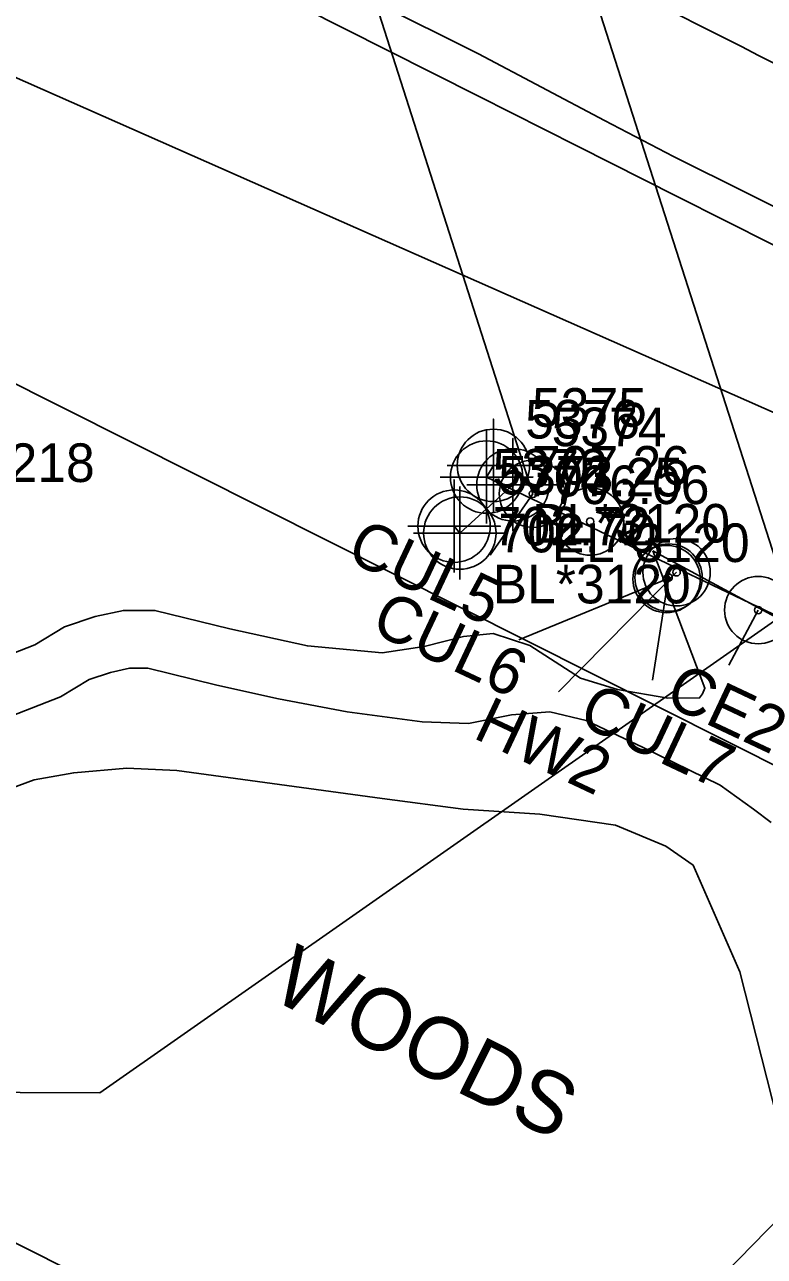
# Model space of a CAD drawing. Extents: x 1516784 to 1522736, y 634838 to 639369.
# Drawn here: x 1519934.1 to 1519982, y 638274.7 to 638354.5 of the extents above; entities that cross this region are included whole.
import ezdxf

# ---------------------------------------------------------------- set-up
doc = ezdxf.new("R2010")
doc.units = 0
for name, color, linetype in [('COGO Default Point Elevation', 7, 'Continuous'), ('COGO Default Point Number', 7, 'Continuous'), ('Exist Environmental Wetland Boundary Cogo Number', 7, 'Continuous'), ('Exist Hydro Stream or Body of Water Text', 7, 'Continuous'), ('Exist Hydro Swamp or Marsh Text', 7, 'Continuous'), ('Exist Other Culture Located Object CELL', 7, 'Continuous'), ('Exist Property Line', 7, 'Continuous'), ('Exist Property Owner Text', 7, 'Continuous'), ('Exist Right of Way Line', 7, 'Continuous'), ('Exist Structure Major Deck Tunnel Box Culvert Leader', 7, 'Continuous'), ('Exist Structure Major Deck Tunnel Box Culvert Text', 7, 'Continuous'), ('Exist Structure Minor Head and End Wall', 7, 'Continuous'), ('Exist Structure Minor Head and End Wall Cogo Comment', 7, 'Continuous'), ('Exist Structure Minor Head and End Wall Cogo Elevation', 7, 'Continuous'), ('Exist Structure Minor Head and End Wall Cogo Number', 7, 'Continuous'), ('Exist Structure Minor Head and End Wall Cogo Point CELL', 7, 'Continuous'), ('Exist Structure Minor Pipes RCP 18 Inch Cogo Comment', 7, 'Continuous'), ('Exist Utilities Sanitary Sewer UG Line', 7, 'Continuous'), ('Exist Utilities Sanitary Sewer UG Line Leader', 7, 'Continuous'), ('Exist Vegetation Woods Line', 7, 'Continuous'), ('Exist Vegetation Woods Line Text', 7, 'Continuous')]:
    doc.layers.add(name, color=color, linetype=linetype)

msp = doc.modelspace()

# ---------------------------------------------------------------- linework, layer by layer
at = {"layer": 'COGO Default Point Elevation'}
msp.add_lwpolyline([(1519976.031, 638355.302), (1519978.261, 638354.171), (1519980.49, 638353.04), (1519981.611, 638352.471), (1519983.843, 638351.344)], dxfattribs=at)
at = {"layer": 'COGO Default Point Number'}
msp.add_lwpolyline([(1520040.075, 638308.275), (1520033.645, 638313.082), (1520026.479, 638317.976), (1520021.943, 638320.873), (1520020.192, 638322.08), (1520020.93, 638323.482), (1520014.717, 638326.708), (1520007.418, 638330.447), (1520000.996, 638333.701), (1519995.941, 638336.169), (1519986.387, 638340.796), (1519980.903, 638343.537), (1519976.096, 638345.939), (1519971.637, 638348.27), (1519963.461, 638352.566), (1519956.751, 638355.913)], dxfattribs=at)
at = {"layer": 'Exist Environmental Wetland Boundary Cogo Number'}
msp.add_lwpolyline([(1519952.118, 638355.557), (1519957.56, 638352.811), (1519963.477, 638349.827), (1519969.868, 638346.605), (1519976.341, 638343.341), (1519982.504, 638340.233), (1519988.357, 638337.281), (1519993.901, 638334.484), (1519999.535, 638331.642), (1520005.661, 638328.551), (1520012.279, 638325.212), (1520019.346, 638321.646)], dxfattribs=at)
at = {"layer": 'Exist Hydro Stream or Body of Water Text'}
msp.add_line((1519983.953, 638315.434), (1519974.767, 638320.407), dxfattribs=at)
for points in [[(1519974.767, 638320.407), (1519978.135, 638311.517), (1519977.967, 638311.139), (1519977.781, 638310.876), (1519975.729, 638310.858)], [(1519975.729, 638310.858), (1519972.475, 638311.417), (1519970.065, 638312.151), (1519966.787, 638314.261), (1519964.418, 638315.043), (1519962.488, 638314.845), (1519959.947, 638314.21), (1519957.232, 638313.786), (1519952.386, 638314.241), (1519947.361, 638315.349), (1519942.513, 638316.545), (1519940.465, 638316.544), (1519938.64, 638316.148), (1519936.659, 638315.482), (1519934.733, 638314.313), (1519930.347, 638312.618), (1519924.083, 638311.537), (1519920.439, 638311.455), (1519915.589, 638311.431)], [(1519923.091, 638307.768), (1519924.446, 638307.798), (1519931.351, 638308.99), (1519936.393, 638310.939), (1519938.247, 638312.064), (1519939.637, 638312.531), (1519940.869, 638312.798), (1519942.059, 638312.799), (1519946.509, 638311.701), (1519950.519, 638310.817)], [(1519950.519, 638310.817), (1519954.961, 638309.982), (1519959.823, 638309.323), (1519962.809, 638309.217), (1519965.608, 638309.784), (1519968.081, 638309.985), (1519970.445, 638309.413), (1519974.122, 638307.672)], [(1519974.122, 638307.672), (1519979.126, 638305.222), (1519981.269, 638303.677), (1519982.426, 638302.817)]]:
    msp.add_lwpolyline(points, dxfattribs=at)
at = {"layer": 'Exist Hydro Swamp or Marsh Text'}
for p, q in [((1519966.995, 638324.094), (1519931.986, 638433.405)), ((1519949.169, 638424.385), (1519984.627, 638313.809))]:
    msp.add_line(p, q, dxfattribs=at)
at = {"layer": 'Exist Other Culture Located Object CELL'}
for centre, radius in [((1519966.995, 638324.094), 2.18), ((1519966.995, 638324.094), 0.24), ((1519970.696, 638322.293), 2.18), ((1519970.696, 638322.293), 0.24), ((1519975.779, 638318.668), 2.18), ((1519976.298, 638319.009), 2.18), ((1519975.65, 638318.574), 2.18), ((1519976.298, 638319.009), 0.24), ((1519975.65, 638318.574), 0.24), ((1519975.779, 638318.668), 0.24), ((1519981.579, 638316.561), 2.18), ((1519981.579, 638316.561), 0.24)]:
    msp.add_circle(centre, radius, dxfattribs=at)
at = {"layer": 'Exist Property Line'}
msp.add_line((1519853.457, 638315.758), (1519987.515, 638248.464), dxfattribs=at)
at = {"layer": 'Exist Right of Way Line'}
msp.add_line((1519230.656, 638683.957), (1520000.914, 638297.346), dxfattribs=at)
at = {"layer": 'Exist Structure Major Deck Tunnel Box Culvert Leader'}
for p, q in [((1519966.995, 638324.094), (1519964.219, 638320.107)), ((1519975.65, 638318.574), (1519966.08, 638314.641)), ((1519976.298, 638319.009), (1519968.658, 638311.278)), ((1519975.779, 638318.668), (1519974.738, 638312.034)), ((1519981.579, 638316.561), (1519979.687, 638312.999))]:
    msp.add_line(p, q, dxfattribs=at)
at = {"layer": 'Exist Structure Minor Head and End Wall'}
for points in [[(1519964.43, 638325.932), (1519963.992, 638325.171), (1519985.936, 638314.688)], [(1519961.886, 638321.995), (1519962.258, 638321.547), (1519965.701, 638324.672)]]:
    msp.add_lwpolyline(points, dxfattribs=at)
at = {"layer": 'Exist Structure Minor Head and End Wall Cogo Point CELL'}
for points in [[(1519961.43, 638325.932), (1519967.43, 638325.932), (1519964.43, 638325.932), (1519964.43, 638328.932), (1519964.43, 638322.932)], [(1519960.992, 638325.171), (1519966.992, 638325.171), (1519963.992, 638325.171), (1519963.992, 638328.171), (1519963.992, 638322.171)], [(1519962.701, 638324.672), (1519968.701, 638324.672), (1519965.701, 638324.672), (1519965.701, 638327.672), (1519965.701, 638321.672)], [(1519958.886, 638321.995), (1519964.886, 638321.995), (1519961.886, 638321.995), (1519961.886, 638324.995), (1519961.886, 638318.995)], [(1519959.258, 638321.547), (1519965.258, 638321.547), (1519962.258, 638321.547), (1519962.258, 638324.547), (1519962.258, 638318.547)]]:
    msp.add_lwpolyline(points, dxfattribs=at)
for centre in [(1519964.43, 638325.932), (1519963.992, 638325.171), (1519965.701, 638324.672), (1519961.886, 638321.995), (1519962.258, 638321.547)]:
    msp.add_circle(centre, 2.344, dxfattribs=at)
at = {"layer": 'Exist Utilities Sanitary Sewer UG Line'}
msp.add_line((1519801.899, 638409.183), (1519994.429, 638324.114), dxfattribs=at)
at = {"layer": 'Exist Utilities Sanitary Sewer UG Line Leader'}
for points in [[(1519994.429, 638324.114), (1519938.941, 638285.309), (1519928.609, 638285.342)], [(1520002.892, 638297.628), (1519969.501, 638263.468), (1519963.501, 638263.468)]]:
    msp.add_lwpolyline(points, dxfattribs=at)
at = {"layer": 'Exist Vegetation Woods Line'}
msp.add_lwpolyline([(1519927.786, 638303.019), (1519934.678, 638305.57), (1519937.256, 638306.032), (1519940.699, 638306.33), (1519943.935, 638306.168), (1519957.227, 638304.357), (1519962.465, 638303.68), (1519967.437, 638303.348), (1519972.346, 638302.638), (1519975.602, 638301.28), (1519977.366, 638300.041), (1519980.383, 638293.139), (1519983.54, 638280.722), (1519990.547, 638267.008), (1519999.151, 638255.779), (1520009.202, 638244.947), (1520021.231, 638234.991), (1520034.369, 638225.944), (1520043.483, 638218.878)], dxfattribs=at)

# ---------------------------------------------------------------- texts
at = {"layer": 'Exist Property Owner Text'}
msp.add_text('WATER COMPANY AQUISITION CORP.', height=5, rotation=335.09801, dxfattribs=at).set_placement((1519863.952, 638273.662))
at = {"layer": 'Exist Structure Major Deck Tunnel Box Culvert Text'}
for s, p in [('CUL5', (1519954.785, 638319.856)), ('CUL6', (1519956.381, 638315.198)), ('CE2', (1519975.406, 638310.517)), ('CUL7', (1519969.801, 638309.237)), ('HW2', (1519963.025, 638308.325))]:
    msp.add_text(s, height=3, rotation=334.78961, dxfattribs=at).set_placement(p)
at = {"layer": 'Exist Structure Minor Head and End Wall Cogo Comment'}
for s, p in [('BL*3120', (1519966.93, 638320.932)), ('EL*3120', (1519968.201, 638319.672)), ('BL*3120', (1519964.386, 638316.995))]:
    msp.add_text(s, height=2.5, dxfattribs=at).set_placement(p)
at = {"layer": 'Exist Structure Minor Head and End Wall Cogo Elevation'}
for s, p in [('707.26', (1519966.93, 638324.682)), ('707.25', (1519966.492, 638323.921)), ('706.06', (1519968.201, 638323.422)), ('702.72', (1519964.386, 638320.745)), ('702.70', (1519964.758, 638320.297))]:
    msp.add_text(s, height=2.5, dxfattribs=at).set_placement(p)
at = {"layer": 'Exist Structure Minor Head and End Wall Cogo Number'}
for s, p in [('5375', (1519966.93, 638328.432)), ('5376', (1519966.492, 638327.671)), ('5374', (1519968.201, 638327.172)), ('5372', (1519964.386, 638324.495)), ('5373', (1519964.758, 638324.047))]:
    msp.add_text(s, height=2.5, dxfattribs=at).set_placement(p)
at = {"layer": 'Exist Structure Minor Pipes RCP 18 Inch Cogo Comment'}
msp.add_text('20"DI PI EL*4218', height=2.5, dxfattribs=at).set_placement((1519912.519, 638324.854))
at = {"layer": 'Exist Vegetation Woods Line Text'}
msp.add_text('WOODS', height=4, rotation=333.50213, dxfattribs=at).set_placement((1519949.891, 638291.45))

doc.saveas('drawing.dxf')
